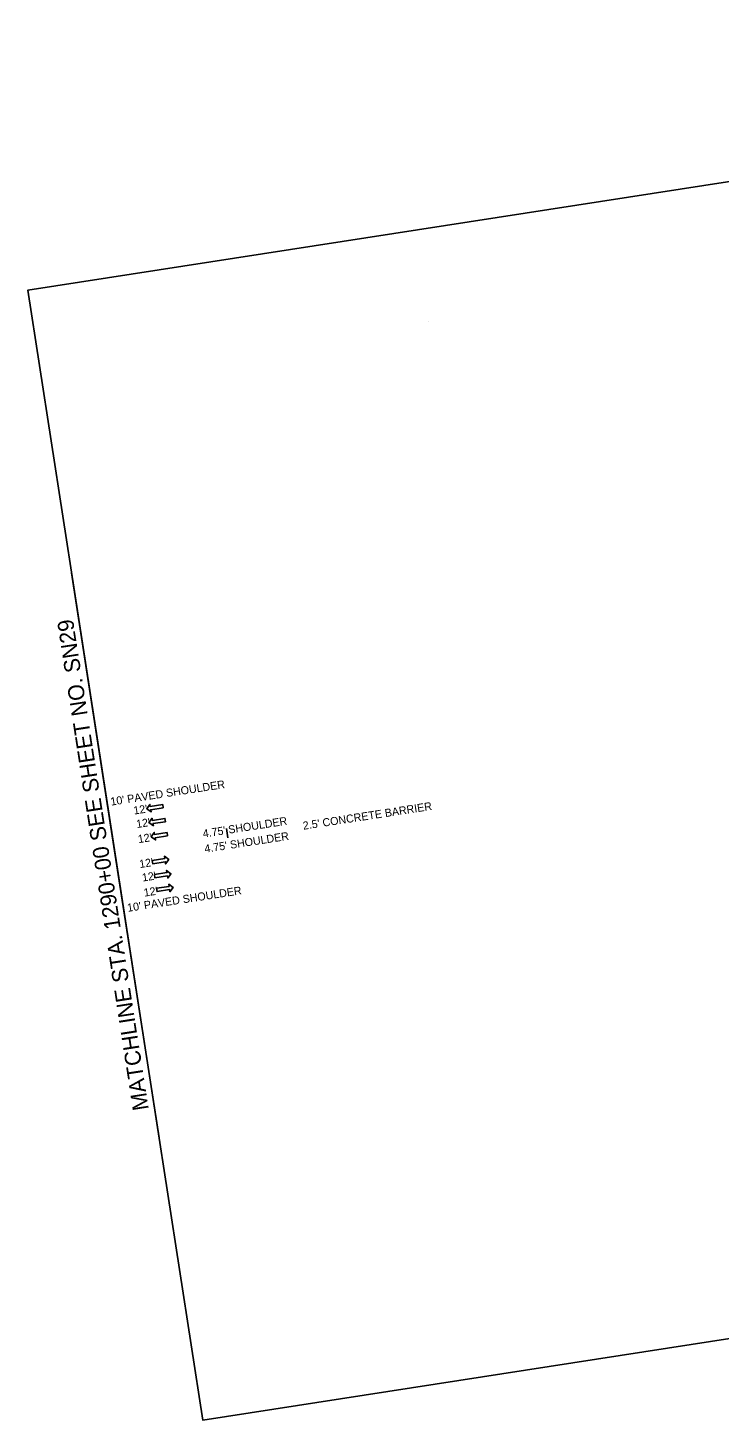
# Model space of a CAD drawing. Extents: x 1778251 to 1779871, y 1179849 to 1181087.
# Drawn here: x 1778251 to 1778856, y 1179849 to 1181067 of the extents above; entities that cross this region are included whole.
import ezdxf

# ---------------------------------------------------------------- set-up
doc = ezdxf.new("R2010")
doc.units = 0
for name, color, linetype in [('Default', 7, 'Continuous'), ('RD_HC_Data', 7, 'Continuous'), ('RD_PD_GR', 7, 'Continuous'), ('RD_PD_MedBWall', 7, 'Continuous'), ('RD_SHT_MatchLine', 7, 'Continuous'), ('RD_Sketch2', 7, 'Continuous')]:
    doc.layers.add(name, color=color, linetype=linetype)

# ---------------------------------------------------------------- blocks, each defined once
blk = doc.blocks.new('SARRW2')
at = {"layer": 'RD_Sketch2'}
blk.add_lwpolyline([(-12, 1.2), (-12, -1.2), (-2.8, -1.2), (-2.8, -2.8), (0, 0), (-2.8, 2.8), (-2.8, 1.2)], close=True, dxfattribs=at)

msp = doc.modelspace()

# ---------------------------------------------------------------- linework, layer by layer
at = {"layer": 'RD_HC_Data'}
msp.add_lwpolyline([(1779870.6, 1180182.2), (1779733.7, 1181066.7), (1778251.3, 1180837.2), (1778404.3, 1179849), (1779093.2, 1179955.6), (1779077.1, 1180059.4)], close=True, dxfattribs=at)
at = {"layer": 'RD_PD_MedBWall'}
msp.add_line((1778426.4, 1180358.4), (1778425.2, 1180366.3), dxfattribs=at)
at = {"layer": 'RD_SHT_MatchLine'}
msp.add_lwpolyline([(1778366.1, 1180096), (1778327.8, 1180343.1), (1778289.6, 1180590.1)], dxfattribs=at)

# ---------------------------------------------------------------- block references
at = {"layer": 'RD_Sketch2', "xscale": 1.2}
for p, yscale, rotation in [((1778355.4, 1180383.7), 1.2, -171.19998882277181), ((1778357.3, 1180371.6), 1.2, -171.19998882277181), ((1778359.2, 1180359.2), 1.2, -171.19998882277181), ((1778374.6, 1180339.3), 1.1999999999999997, 8.800011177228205), ((1778376.5, 1180326.9), 1.1999999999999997, 8.800011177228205), ((1778378.4, 1180314.9), 1.1999999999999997, 8.800011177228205)]:
    msp.add_blockref('SARRW2', p, dxfattribs=dict(at, yscale=yscale, rotation=rotation))

# ---------------------------------------------------------------- texts
at = {"layer": 'Default'}
for s, p in [('Angle:  16.0848', (1778602.4, 1180810.3)), ('Align: A_I85', (1778602.4, 1180810.5)), ('Sheet: 3', (1778602.5, 1180810))]:
    msp.add_text(s, height=0.208, rotation=188.8, dxfattribs=at).set_placement(p)
at = {"layer": 'RD_PD_GR'}
for s, p in [("10' PAVED SHOULDER", (1778324.2, 1180386.4)), ("12'", (1778344.3, 1180378.6)), ("2.5' CONCRETE BARRIER", (1778492.5, 1180365.3)), ("12'", (1778346.7, 1180366.8)), ("4.75' SHOULDER", (1778404.9, 1180358.4)), ("12'", (1778348.2, 1180353.6)), ("4.75' SHOULDER", (1778406.4, 1180345.2)), ("12'", (1778349.4, 1180331.8)), ("12'", (1778351.8, 1180320)), ("10' PAVED SHOULDER", (1778338.8, 1180293.5)), ("12'", (1778353.3, 1180306.8))]:
    msp.add_text(s, height=7, rotation=8.8, dxfattribs=at).set_placement(p)
at = {"layer": 'RD_SHT_MatchLine'}
msp.add_text('MATCHLINE STA. 1290+00 SEE SHEET NO. SN29', height=14, rotation=98.8, dxfattribs=at).set_placement((1778357.2, 1180120.9))

doc.saveas('drawing.dxf')
